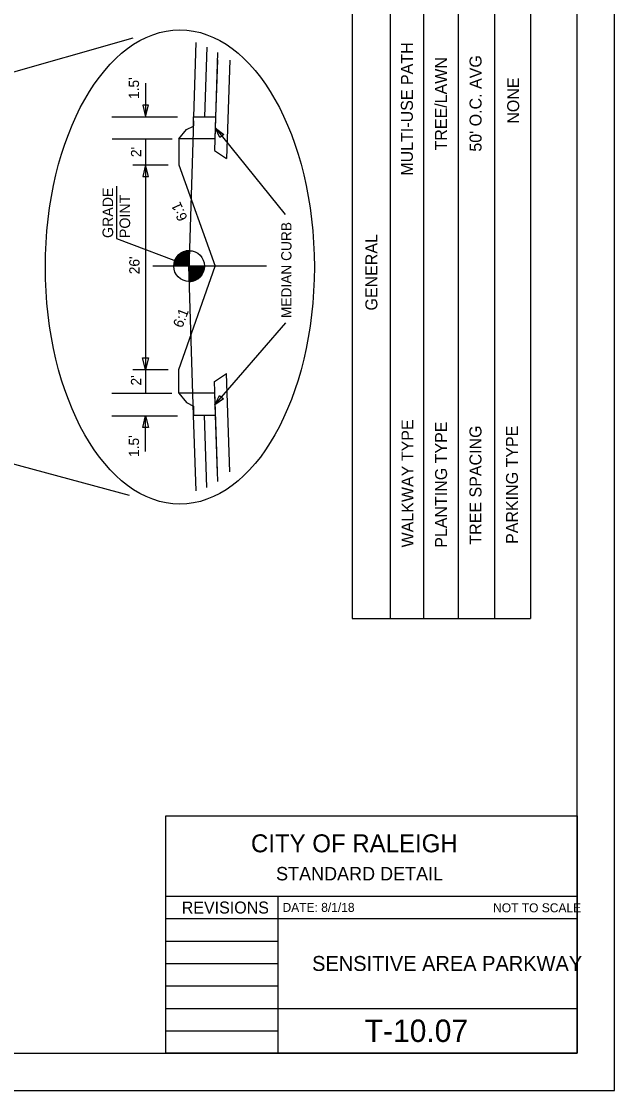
# Model space of a CAD drawing. Extents: x 0 to 8.5, y 0 to 11.
# Drawn here: x 4.53 to 8.5, y 0 to 7.15 of the extents above; entities that cross this region are included whole.
import ezdxf

# ---------------------------------------------------------------- set-up
doc = ezdxf.new("R2010")
doc.units = 0
for name, color, linetype in [('Default', 7, 'Continuous'), ('DIM', 7, 'Continuous'), ('GROUND', 7, 'Continuous'), ('INSET', 7, 'Continuous'), ('ROAD SECTION', 7, 'Continuous'), ('SHEET BORDER', 7, 'Continuous'), ('SHEET NOTES', 7, 'Continuous'), ('SHEET TITLE BLOCK LINE', 7, 'Continuous'), ('SHEET TITLE BLOCK TEXT', 7, 'Continuous'), ('SHEET TRIM BORDER', 7, 'Continuous'), ('Typical Grade Point Symbol CELL', 7, 'Continuous')]:
    doc.layers.add(name, color=color, linetype=linetype)

msp = doc.modelspace()

# ---------------------------------------------------------------- linework, layer by layer
at = {"layer": 'Default'}
for points in [[(5.5868, 6.362), (5.6381, 6.4257), (5.6854, 6.4485), (5.6854, 6.509), (5.8324, 6.509), (5.8276, 6.362)], [(5.5868, 4.6632), (5.6381, 4.5995), (5.6854, 4.5766), (5.6854, 4.5162), (5.8324, 4.5162), (5.8276, 4.6632)]]:
    msp.add_lwpolyline(points, close=True, dxfattribs=at)
at = {"layer": 'DIM'}
for p, q in [((5.3643, 6.7357), (5.3643, 6.509)), ((5.1392, 6.509), (5.577, 6.509)), ((5.8311, 6.4352), (6.2967, 5.8575)), ((5.1397, 6.3622), (5.5427, 6.3622)), ((5.3642, 6.3622), (5.3641, 4.6629)), ((5.2798, 6.1898), (5.5145, 6.1898)), ((5.1701, 6.0455), (5.1701, 5.6959)), ((5.1701, 5.6959), (5.654, 5.514)), ((6.1724, 5.5126), (5.4135, 5.5126)), ((5.8271, 4.5838), (6.3027, 5.1334)), ((5.2798, 4.82), (5.5144, 4.82)), ((5.1391, 4.6629), (5.5404, 4.6629)), ((5.1391, 4.512), (5.5769, 4.512)), ((5.3643, 4.2733), (5.3643, 4.512))]:
    msp.add_line(p, q, dxfattribs=at)
for points in [[(5.3446, 6.5878), (5.3643, 6.5091), (5.3839, 6.5878)], [(5.8608, 6.371), (5.8311, 6.4352), (5.8875, 6.3926)], [(5.3839, 6.111), (5.3642, 6.1898), (5.3445, 6.111)], [(5.3838, 4.8987), (5.3641, 4.82), (5.3444, 4.8987)], [(5.8849, 4.6244), (5.8271, 4.5838), (5.859, 4.6469)], [(5.3446, 4.4333), (5.3643, 4.5121), (5.3839, 4.4333)]]:
    msp.add_lwpolyline(points, close=True, dxfattribs=at)
at = {"layer": 'GROUND'}
for p, q in [((5.6854, 6.4838), (5.654, 5.4874)), ((5.6854, 4.5162), (5.654, 5.5126))]:
    msp.add_line(p, q, dxfattribs=at)
at = {"layer": 'INSET'}
for p, q in [((3.8898, 6.6428), (5.2813, 7.0385)), ((5.2555, 3.9782), (3.9012, 4.3437))]:
    msp.add_line(p, q, dxfattribs=at)
msp.add_ellipse((5.5932, 5.5059), major_axis=(0, -1.585), ratio=0.567342, dxfattribs=at)
at = {"layer": 'ROAD SECTION'}
for p, q in [((5.701, 7.0061), (5.6854, 6.509)), ((5.7736, 6.9759), (5.7589, 6.509)), ((5.8458, 6.9404), (5.8252, 6.2857)), ((5.8444, 6.891), (5.8324, 6.509)), ((5.9265, 6.8887), (5.9058, 6.2319)), ((5.8252, 6.2857), (5.9058, 6.2319)), ((5.8252, 4.7395), (5.9058, 4.7932)), ((5.9265, 4.1364), (5.9058, 4.7932)), ((5.8462, 4.0717), (5.8252, 4.7395)), ((5.7012, 4.0086), (5.6852, 4.5162)), ((5.774, 4.0314), (5.7587, 4.5162)), ((5.8446, 4.1269), (5.8324, 4.5162))]:
    msp.add_line(p, q, dxfattribs=at)
for points in [[(5.5868, 6.362), (5.6381, 6.4257), (5.6854, 6.4485), (5.6854, 6.509), (5.8324, 6.509), (5.8276, 6.362)], [(5.5868, 4.6632), (5.6381, 4.5995), (5.6854, 4.5766), (5.6854, 4.5162), (5.8324, 4.5162), (5.8276, 4.6632)]]:
    msp.add_lwpolyline(points, close=True, dxfattribs=at)
for points in [[(5.5868, 6.362), (5.5868, 6.1898), (5.8289, 5.5126)], [(5.5868, 4.6632), (5.5868, 4.82), (5.8289, 5.5126)]]:
    msp.add_lwpolyline(points, dxfattribs=at)
at = {"layer": 'SHEET BORDER'}
msp.add_lwpolyline([(8.25, 10.75), (0.25, 10.75), (0.25, 0.25), (8.25, 0.25)], close=True, dxfattribs=at)
at = {"layer": 'SHEET NOTES'}
for p, q in [((6.7456, 7.8588), (6.7456, 3.1566)), ((6.999, 7.8588), (6.999, 3.1566)), ((7.2231, 7.8588), (7.2231, 3.1566)), ((7.4545, 7.8588), (7.4545, 3.1566)), ((7.6958, 7.8588), (7.6958, 3.1566)), ((7.9371, 7.8588), (7.9371, 3.1566)), ((6.7456, 3.1566), (7.9371, 3.1566))]:
    msp.add_line(p, q, dxfattribs=at)
at = {"layer": 'SHEET TITLE BLOCK LINE'}
for p, q in [((5.5002, 1.2999), (8.25, 1.2999)), ((6.2501, 0.25), (6.2501, 1.2999)), ((5.5002, 1.1499), (8.25, 1.1499)), ((5.5002, 0.9999), (6.2501, 0.9999)), ((5.5002, 0.85), (6.2501, 0.85)), ((5.5002, 0.7), (6.2501, 0.7)), ((5.5002, 0.55), (6.2501, 0.55)), ((6.2501, 0.55), (8.25, 0.55)), ((5.5002, 0.4), (6.2501, 0.4))]:
    msp.add_line(p, q, dxfattribs=at)
msp.add_lwpolyline([(8.25, 0.25), (5.5002, 0.25), (5.5002, 1.8359), (8.25, 1.8359)], close=True, dxfattribs=at)
at = {"layer": 'SHEET TRIM BORDER'}
msp.add_lwpolyline([(8.5, 11), (0, 11), (0, 0), (8.5, 0)], close=True, dxfattribs=at)
at = {"layer": 'Typical Grade Point Symbol CELL'}
for p, q in [((5.6551, 5.6152), (5.6551, 5.5123)), ((5.6551, 5.5123), (5.5522, 5.5123)), ((5.758, 5.512), (5.6551, 5.5123)), ((5.6551, 5.4094), (5.6551, 5.5123)), ((5.6551, 5.5123), (5.758, 5.512))]:
    msp.add_line(p, q, dxfattribs=at)
for points in [[(5.5751, 5.577), (5.6551, 5.577)], [(5.5769, 5.5791), (5.6551, 5.5791)], [(5.5787, 5.5811), (5.6551, 5.5811)], [(5.5806, 5.5832), (5.6551, 5.5832)], [(5.5826, 5.5852), (5.6551, 5.5852)], [(5.5847, 5.5873), (5.6551, 5.5873)], [(5.587, 5.5894), (5.6551, 5.5894)], [(5.5895, 5.5914), (5.6551, 5.5914)], [(5.592, 5.5935), (5.6551, 5.5935)], [(5.5947, 5.5955), (5.6551, 5.5955)], [(5.5977, 5.5976), (5.6551, 5.5976)], [(5.6009, 5.5997), (5.6551, 5.5996)], [(5.6043, 5.6017), (5.6551, 5.6017)], [(5.608, 5.6038), (5.6551, 5.6038)], [(5.6124, 5.6058), (5.6551, 5.6058)], [(5.6172, 5.6079), (5.6551, 5.6079)], [(5.6229, 5.6099), (5.6551, 5.6099)], [(5.63, 5.612), (5.6551, 5.612)], [(5.6405, 5.6141), (5.6551, 5.6141)], [(5.5522, 5.5153), (5.6551, 5.5153)], [(5.5522, 5.5132), (5.5522, 5.5132), (5.6551, 5.5132)], [(5.5524, 5.5194), (5.6551, 5.5194)], [(5.5524, 5.5173), (5.6551, 5.5173)], [(5.5527, 5.5214), (5.6551, 5.5214)], [(5.5529, 5.5235), (5.6551, 5.5235)], [(5.5531, 5.5255), (5.6551, 5.5255)], [(5.5533, 5.5276), (5.6551, 5.5276)], [(5.5536, 5.5297), (5.6551, 5.5297)], [(5.554, 5.5317), (5.6551, 5.5317)], [(5.5545, 5.5338), (5.6551, 5.5338)], [(5.5549, 5.5358), (5.6551, 5.5358)], [(5.5554, 5.5379), (5.6551, 5.5379)], [(5.5561, 5.54), (5.6551, 5.5399)], [(5.5565, 5.542), (5.6551, 5.542)], [(5.5572, 5.5441), (5.6551, 5.5441)], [(5.5579, 5.5461), (5.6551, 5.5461)], [(5.5586, 5.5482), (5.6551, 5.5482)], [(5.5595, 5.5502), (5.6551, 5.5502)], [(5.5604, 5.5523), (5.6551, 5.5523)], [(5.5614, 5.5544), (5.6551, 5.5544)], [(5.5623, 5.5564), (5.6551, 5.5564)], [(5.5632, 5.5585), (5.6551, 5.5585)], [(5.5643, 5.5605), (5.6551, 5.5605)], [(5.5655, 5.5626), (5.6551, 5.5626)], [(5.5666, 5.5647), (5.6551, 5.5646)], [(5.5677, 5.5667), (5.6551, 5.5667)], [(5.5691, 5.5688), (5.6551, 5.5688)], [(5.5705, 5.5708), (5.6551, 5.5708)], [(5.5721, 5.5729), (5.6551, 5.5729)], [(5.5735, 5.5749), (5.6551, 5.5749)], [(5.6551, 5.5107), (5.758, 5.5107), (5.758, 5.5107)], [(5.6551, 5.5086), (5.758, 5.5086)], [(5.6551, 5.5066), (5.7578, 5.5066)], [(5.6551, 5.5045), (5.7578, 5.5045)], [(5.6551, 5.5024), (5.7576, 5.5024)], [(5.6551, 5.5004), (5.7573, 5.5004)], [(5.6551, 5.4983), (5.7571, 5.4983)], [(5.6551, 5.4963), (5.7567, 5.4963)], [(5.6551, 5.4942), (5.7564, 5.4942)], [(5.6551, 5.4922), (5.756, 5.4922)], [(5.6551, 5.4901), (5.7555, 5.4901)], [(5.6551, 5.488), (5.7551, 5.488)], [(5.6551, 5.486), (5.7546, 5.486)], [(5.6551, 5.4839), (5.7539, 5.4839)], [(5.6551, 5.4819), (5.7535, 5.4819)], [(5.6551, 5.4798), (5.7528, 5.4798)], [(5.6551, 5.4777), (5.7521, 5.4777)], [(5.6551, 5.4757), (5.7514, 5.4757)], [(5.6551, 5.4736), (5.7505, 5.4736)], [(5.6551, 5.4716), (5.7496, 5.4716)], [(5.6551, 5.4695), (5.7487, 5.4695)], [(5.6551, 5.4675), (5.7477, 5.4675)], [(5.6551, 5.4654), (5.7468, 5.4654)], [(5.6551, 5.4633), (5.7457, 5.4633)], [(5.6551, 5.4613), (5.7445, 5.4613)], [(5.6551, 5.4592), (5.7434, 5.4592)], [(5.6551, 5.4572), (5.742, 5.4572)], [(5.6551, 5.4551), (5.7406, 5.4551)], [(5.6551, 5.453), (5.7393, 5.453)], [(5.6551, 5.451), (5.7379, 5.451)], [(5.6551, 5.4489), (5.7363, 5.4489)], [(5.6551, 5.4469), (5.7347, 5.4469)], [(5.6551, 5.4448), (5.7329, 5.4448)], [(5.6551, 5.4428), (5.731, 5.4428)], [(5.6551, 5.4407), (5.7292, 5.4407)], [(5.6551, 5.4386), (5.7272, 5.4386)], [(5.6551, 5.4366), (5.7249, 5.4366)], [(5.6551, 5.4345), (5.7226, 5.4345)], [(5.6551, 5.4325), (5.7201, 5.4325)], [(5.6551, 5.4304), (5.7175, 5.4304)], [(5.6551, 5.4283), (5.7148, 5.4283)], [(5.6551, 5.4263), (5.7118, 5.4263)], [(5.6551, 5.4242), (5.7086, 5.4242)], [(5.6551, 5.4222), (5.705, 5.4222)], [(5.6551, 5.4201), (5.7011, 5.4201)], [(5.6551, 5.4181), (5.6967, 5.4181)], [(5.6551, 5.416), (5.6919, 5.416)], [(5.6551, 5.4139), (5.6858, 5.4139)], [(5.6551, 5.4119), (5.6784, 5.4119)], [(5.6551, 5.4098), (5.6663, 5.4098)]]:
    msp.add_lwpolyline(points, dxfattribs=at)
msp.add_circle((5.6551, 5.5122), 0.1029, dxfattribs=at)
for start, end in [(89.98837, 179.98837), (269.98837, 359.98837)]:
    msp.add_arc((5.6551, 5.5122), 0.1029, start, end, dxfattribs=at)

# ---------------------------------------------------------------- texts
at = {"layer": 'DIM'}
for s, height, rotation, p in [("1.5'", 0.0686, 90.00211, (5.3203, 6.6291)), ("2'", 0.0686, 89.99789, (5.3348, 6.2407)), ('GRADE', 0.0709, 89.99789, (5.1471, 5.6999)), ('POINT', 0.0709, 89.99789, (5.2607, 5.6993)), ('6:1', 0.0686, 114.42751, (5.6468, 5.8317)), ('MEDIAN CURB', 0.0686, 90, (6.3395, 5.1645)), ("26'", 0.0686, 89.99789, (5.3234, 5.4575)), ('6:1', 0.0686, 68.75298, (5.6086, 5.0941)), ("2'", 0.0686, 89.99789, (5.3345, 4.7136)), ("1.5'", 0.0686, 90.00211, (5.3203, 4.236))]:
    msp.add_text(s, height=height, rotation=rotation, dxfattribs=at).set_placement(p)
at = {"layer": 'SHEET NOTES'}
for s, height, p in [('MULTI-USE PATH', 0.079998, (7.151, 6.1163)), ('TREE/LAWN', 0.08, (7.3786, 6.285)), ("50' O.C. AVG", 0.079998, (7.6103, 6.2773)), ('NONE', 0.08, (7.8617, 6.4639)), ('GENERAL', 0.08, (6.9137, 5.2149)), ('WALKWAY TYPE', 0.079998, (7.1551, 3.6313)), ('PLANTING TYPE', 0.079998, (7.3795, 3.6289)), ('TREE SPACING', 0.079998, (7.6098, 3.6502)), ('PARKING TYPE', 0.079998, (7.8537, 3.6548))]:
    msp.add_text(s, height=height, rotation=90, dxfattribs=at).set_placement(p)
at = {"layer": 'SHEET TITLE BLOCK TEXT'}
for s, height, p in [('CITY OF RALEIGH', 0.12, (6.0686, 1.5932)), ('STANDARD DETAIL', 0.09, (6.2364, 1.4053)), ('REVISIONS', 0.08, (5.6059, 1.184)), ('DATE: 8/1/18', 0.06, (6.2796, 1.195)), ('NOT TO SCALE', 0.06, (7.6877, 1.1922)), ('SENSITIVE AREA PARKWAY', 0.100002, (6.4772, 0.8)), ('T-10.07', 0.15, (6.8291, 0.325))]:
    msp.add_text(s, height=height, dxfattribs=at).set_placement(p)

doc.saveas('drawing.dxf')
